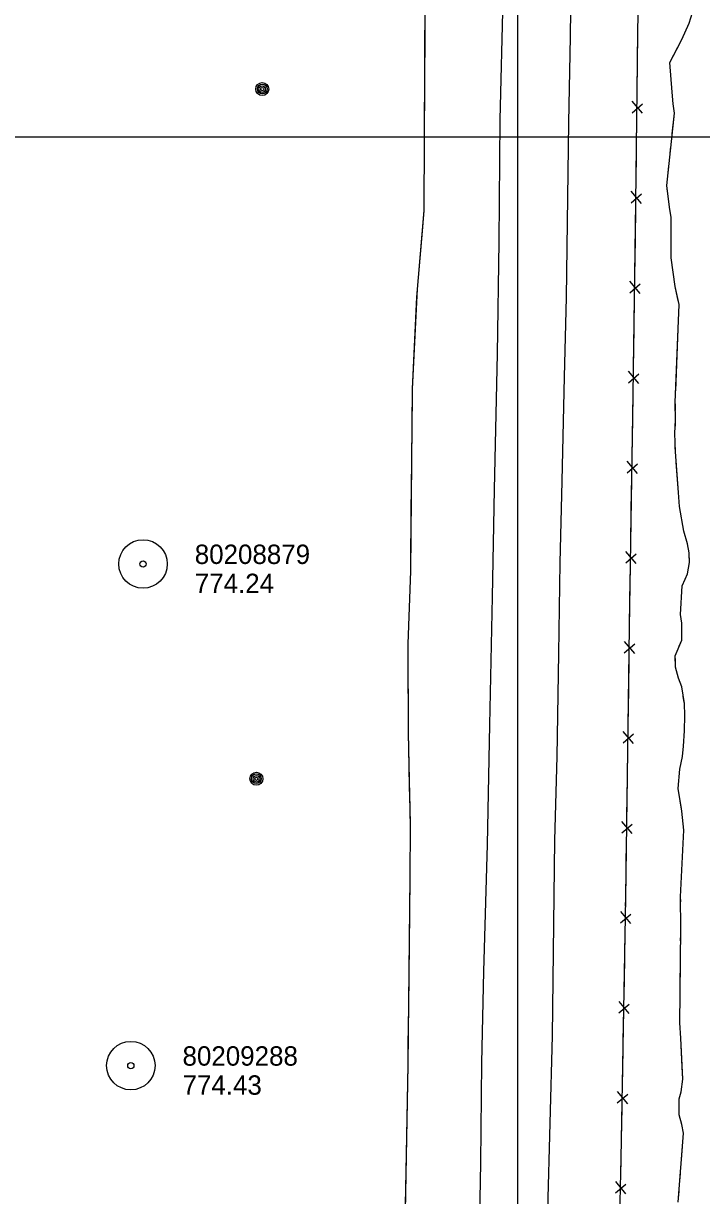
# Model space of a CAD drawing. Extents: x 591954 to 597000, y 198576 to 213500.
# Drawn here: x 593847 to 594056.8, y 208672.4 to 209035.1 of the extents above; entities that cross this region are included whole.
import ezdxf

# ---------------------------------------------------------------- set-up
doc = ezdxf.new("R2010")
doc.units = 0
for name, color, linetype in [('Level 10', 7, 'Continuous'), ('Level 11', 7, 'Continuous'), ('Level 14', 7, 'Continuous'), ('Level 15', 7, 'Continuous'), ('Level 19', 7, 'Continuous'), ('Level 6', 7, 'Continuous')]:
    doc.layers.add(name, color=color, linetype=linetype)

msp = doc.modelspace()

# ---------------------------------------------------------------- linework, layer by layer
at = {"layer": 'Level 10'}
for p, q in [((594000, 208500), (594000, 210000)), ((593000, 209000), (595000, 209000)), ((593000, 209000), (595000, 209000)), ((594000, 207500), (594000, 209000))]:
    msp.add_line(p, q, dxfattribs=at)
at = {"layer": 'Level 11'}
for points in [[(594009.01, 208631.52), (594009.27, 208667.78), (594010.66, 208721.83), (594011.4, 208782.36), (594012.13, 208808.26), (594012.62, 208840.15), (594013.04, 208868.19), (594013.68, 208893.39), (594014.42, 208925.71), (594015, 208950.25), (594015.72, 209004.45), (594016.24, 209030.86), (594016.62, 209056.33), (594017.53, 209087.3), (594018.52, 209145.92), (594019.42, 209185.52), (594019.83, 209212.01), (594020.29, 209245.3), (594020.92, 209277.11)], [(593998.85, 209230.64), (593998.3, 209195.94), (593997.61, 209162.68), (593996.73, 209120.37), (593996.08, 209080.6), (593995.31, 209042.89), (593994.35, 209005.26), (593994.1, 208967.53), (593993.55, 208932.78), (593992.64, 208890.84), (593992, 208857.63), (593991.15, 208818.04), (593990.48, 208781.03), (593989.3, 208741.66), (593988.74, 208713.42), (593988.39, 208682.48), (593987.81, 208648.94), (593987.57, 208630.06)]]:
    msp.add_lwpolyline(points, dxfattribs=at)
at = {"layer": 'Level 14'}
for centre, radius in [((593920.87, 209014.76), 2.02), ((593920.87, 209014.77), 1.52), ((593920.87, 209014.74), 1.01), ((593920.88, 209014.74), 0.502), ((593919.05, 208801.34), 2.02), ((593919.05, 208801.35), 1.52), ((593919.06, 208801.31), 1.01), ((593919.06, 208801.32), 0.502)]:
    msp.add_circle(centre, radius, dxfattribs=at)
at = {"layer": 'Level 15'}
for p, q in [((594035.32, 209007.44), (594038.52, 209010.2)), ((594038.56, 209007.24), (594035.36, 209010.99)), ((594035, 208979.59), (594038.2, 208982.35)), ((594038.24, 208979.38), (594035.04, 208983.13)), ((594034.59, 208951.73), (594037.81, 208954.48)), ((594037.83, 208951.52), (594034.65, 208955.28)), ((594034.19, 208923.88), (594037.4, 208926.63)), ((594037.42, 208923.66), (594034.24, 208927.42)), ((594033.76, 208896.02), (594036.98, 208898.77)), ((594037, 208895.8), (594033.82, 208899.57)), ((594033.34, 208868.17), (594036.55, 208870.91)), ((594036.57, 208867.95), (594033.39, 208871.71)), ((594036.16, 208840.09), (594032.97, 208843.85)), ((594032.92, 208840.31), (594036.13, 208843.06)), ((594032.54, 208812.45), (594035.75, 208815.2)), ((594035.77, 208812.23), (594032.59, 208816)), ((594032.15, 208784.59), (594035.36, 208787.34)), ((594035.39, 208784.38), (594032.2, 208788.14)), ((594034.97, 208756.51), (594031.8, 208760.29)), ((594031.74, 208756.74), (594034.95, 208759.48)), ((594031.24, 208728.88), (594034.46, 208731.62)), ((594034.47, 208728.66), (594031.3, 208732.43)), ((594030.74, 208701.03), (594033.96, 208703.77)), ((594033.97, 208700.8), (594030.8, 208704.58)), ((594033.42, 208672.94), (594030.27, 208676.73)), ((594030.19, 208673.18), (594033.42, 208675.9))]:
    msp.add_line(p, q, dxfattribs=at)
for points in [[(594030.79, 208634.01), (594031.94, 208683.98), (594033.37, 208764.41), (594034.53, 208848.11), (594035.64, 208920.32), (594036.5, 208979.5), (594037.1, 209031.73), (594037.78, 209078.39), (594038.97, 209145.83), (594039.39, 209201.19), (594040, 209259.04), (594040.17, 209306.37), (594041.42, 209344.67), (594041.5, 209389.61), (594042.2, 209438.38), (594043.44, 209486.71), (594045.27, 209558.54)], [(594037.01, 209024), (594037.1, 209031.73), (594037.13, 209033.96)], [(594036.88, 209012.68), (594037.01, 209024)], [(594036.69, 208996.14), (594036.8, 209006.1)], [(594036.56, 208984.82), (594036.69, 208996.14)], [(594036.33, 208968.28), (594036.48, 208978.24)], [(594036.17, 208956.96), (594036.33, 208968.28)], [(594035.93, 208940.43), (594036.07, 208950.38)], [(594035.76, 208929.11), (594035.93, 208940.43)], [(594035.52, 208912.57), (594035.64, 208920.32), (594035.67, 208922.52)], [(594035.34, 208901.25), (594035.52, 208912.57)], [(594035.09, 208884.71), (594035.24, 208894.67)], [(594034.92, 208873.39), (594035.09, 208884.71)], [(594034.66, 208856.86), (594034.82, 208866.81)], [(594034.49, 208845.54), (594034.53, 208848.11), (594034.66, 208856.86)], [(594034.27, 208829), (594034.4, 208838.96)], [(594034.11, 208817.68), (594034.27, 208829)], [(594033.88, 208801.14), (594034.02, 208811.1)], [(594033.72, 208789.82), (594033.88, 208801.14)], [(594033.5, 208773.28), (594033.63, 208783.24)], [(594033.33, 208761.96), (594033.37, 208764.41), (594033.5, 208773.28)], [(594033.03, 208745.43), (594033.21, 208755.38)], [(594032.83, 208734.11), (594033.03, 208745.43)], [(594032.54, 208717.57), (594032.71, 208727.53)], [(594032.33, 208706.25), (594032.54, 208717.57)], [(594032.04, 208689.72), (594032.22, 208699.67)], [(594031.81, 208678.4), (594031.94, 208683.98), (594032.04, 208689.72)]]:
    msp.add_lwpolyline(points, dxfattribs=at)
at = {"layer": 'Level 19'}
for p, q in [((593971.17, 209038.7), (593971.14, 209032.7)), ((593971.14, 209032.7), (593970.98, 208999.7)), ((593970.32, 208970.73), (593969.81, 208964.75)), ((593969.81, 208964.75), (593969.3, 208958.77)), ((593969.3, 208958.77), (593968.79, 208952.79)), ((593967.22, 208919.83), (593966.94, 208890.83)), ((593966.94, 208890.83), (593966.88, 208884.83)), ((593966.88, 208884.83), (593966.83, 208878.83)), ((593966.83, 208878.83), (593966.77, 208872.83)), ((593966.09, 208810.85), (593966.23, 208804.85)), ((593966.23, 208804.85), (593966.38, 208798.85)), ((593966.38, 208798.85), (593966.53, 208792.85)), ((593966.41, 208759.86), (593966.09, 208730.86)), ((593966.09, 208730.86), (593966.02, 208724.86)), ((593966.02, 208724.86), (593965.96, 208718.86)), ((593965.96, 208718.86), (593965.89, 208712.86)), ((593965.89, 208712.86), (593965.29, 208679.86)), ((593965.29, 208679.86), (593964.75, 208650.87))]:
    msp.add_line(p, q, dxfattribs=at)
for points in [[(593975.8, 209239.61), (593975.31, 209230.02), (593975.08, 209223.36), (593974.82, 209218.94), (593974.39, 209199.99), (593974.65, 209179.67), (593974.54, 209161.11), (593974.09, 209136.67), (593973.75, 209125.41), (593972.98, 209109.24), (593971.31, 209066.7), (593970.86, 208977.14), (593968.59, 208950.35), (593967.24, 208921.98), (593966.7, 208865.53), (593965.91, 208843.14), (593965.98, 208815.45), (593966.68, 208786.54), (593966.53, 208770.93), (593965.89, 208712.84), (593964.64, 208644.79), (593963.27, 208633.42), (593963.54, 208628.1)], [(594050.16, 209029.01), (594050.72, 209030.09), (594053.02, 209035.09), (594054.05, 209038.48), (594054.16, 209042.33), (594053.75, 209044.46), (594051.26, 209046.33)], [(594049.62, 208670.34), (594051.22, 208691.65), (594050.74, 208694.34), (594049.92, 208697.34), (594049.86, 208702.35), (594050.5, 208704.45), (594051.02, 208708.41), (594050.45, 208721.03), (594050.13, 208725.79), (594050.18, 208734.84), (594050.39, 208755.09), (594050.35, 208764.79), (594051.34, 208785.46), (594050.77, 208791.33), (594049.58, 208798.29), (594050.12, 208804.36), (594050.94, 208808.25), (594051.27, 208811.41), (594051.56, 208816.21), (594051.62, 208820.94), (594051.51, 208824.64), (594050.74, 208829.79), (594049.7, 208832.45), (594048.8, 208835.92), (594048.7, 208839.42), (594050.72, 208844.18), (594050.7, 208849.52), (594050.28, 208852.12), (594050.85, 208861.05), (594051.76, 208863.07), (594052.51, 208864.71), (594053.06, 208868.25), (594052.99, 208871.2), (594052.45, 208874.03), (594051.39, 208877.95), (594050.02, 208885.6), (594049.73, 208889.9), (594048.73, 208902.54), (594048.55, 208908.24), (594048.78, 208912.33), (594048.7, 208917.81), (594049.62, 208940.58), (594049.85, 208948.1), (594048.69, 208953.61), (594047.44, 208962.53), (594047.46, 208971.24), (594047.38, 208974.99), (594046.92, 208978.2), (594046.03, 208984.89), (594048.46, 209007.24), (594048.06, 209010.21), (594047.76, 209013.8), (594046.96, 209022.94), (594050.72, 209030.09), (594053.02, 209035.09)], [(594047.77, 209000.91), (594048.46, 209007.24), (594048.06, 209010.21), (594047.76, 209013.8), (594046.96, 209022.94), (594050.16, 209029.01)], [(593970.98, 208999.7), (593970.86, 208977.14), (593970.32, 208970.73)], [(594047.12, 208994.95), (594047.34, 208996.93)], [(594046.47, 208988.98), (594046.69, 208990.97)], [(594046.28, 208983.02), (594046.03, 208984.89), (594046.04, 208985.01)], [(594049.39, 208950.26), (594048.69, 208953.61), (594047.44, 208962.53), (594047.46, 208971.24), (594047.38, 208974.99), (594046.92, 208978.2), (594046.81, 208979.06)], [(593968.79, 208952.79), (593967.24, 208921.98), (593967.22, 208919.83)], [(594048.85, 208921.33), (594049.62, 208940.58), (594049.85, 208948.1), (594049.39, 208950.26)], [(594048.74, 208915.33), (594048.71, 208917.33)], [(594048.61, 208909.33), (594048.72, 208911.33)], [(594048.7, 208903.34), (594048.64, 208905.34)], [(594053, 208870.7), (594052.99, 208871.2), (594052.45, 208874.03), (594051.39, 208877.95), (594050.02, 208885.6), (594049.73, 208889.9), (594048.98, 208899.35)], [(593966.77, 208872.83), (593966.7, 208865.53), (593965.91, 208843.14), (593965.91, 208839.85)], [(594049.94, 208842.32), (594050.72, 208844.18), (594050.7, 208849.52), (594050.28, 208852.12), (594050.85, 208861.05), (594051.76, 208863.07), (594052.51, 208864.71), (594053.06, 208868.25), (594053, 208870.7)], [(593965.91, 208839.85), (593965.98, 208815.45), (593966.09, 208810.85)], [(594048.78, 208836.58), (594048.72, 208838.58)], [(594050.34, 208830.81), (594049.7, 208832.45), (594049.64, 208832.68)], [(594051.46, 208824.94), (594051.17, 208826.92)], [(594050.63, 208792.17), (594049.58, 208798.29), (594050.12, 208804.36), (594050.94, 208808.25), (594051.27, 208811.41), (594051.56, 208816.21), (594051.62, 208820.94), (594051.62, 208820.95)], [(593966.53, 208792.85), (593966.68, 208786.54), (593966.53, 208770.93), (593966.41, 208759.86)], [(594050.36, 208763.23), (594050.35, 208764.79), (594051.34, 208785.46), (594050.77, 208791.33), (594050.63, 208792.17)], [(594050.38, 208757.23), (594050.37, 208759.23)], [(594050.35, 208751.23), (594050.37, 208753.23)], [(594050.29, 208745.23), (594050.31, 208747.23)], [(594050.85, 208712.25), (594050.45, 208721.03), (594050.13, 208725.79), (594050.18, 208734.84), (594050.24, 208741.23)], [(594050.61, 208683.56), (594051.22, 208691.65), (594050.74, 208694.34), (594049.92, 208697.34), (594049.86, 208702.35), (594050.5, 208704.45), (594051.02, 208708.41), (594050.85, 208712.25)], [(594050.16, 208677.58), (594050.31, 208679.57)], [(594049.71, 208671.6), (594049.86, 208673.59)]]:
    msp.add_lwpolyline(points, dxfattribs=at)
at = {"layer": 'Level 6'}
for centre, radius in [((593883.98, 208867.8), 7.5), ((593883.98, 208867.8), 7.5), ((593883.98, 208867.8), 0.96), ((593883.98, 208867.8), 0.96), ((593880.2, 208712.57), 7.5), ((593880.2, 208712.57), 7.5), ((593880.2, 208712.57), 0.96), ((593880.2, 208712.57), 0.96)]:
    msp.add_circle(centre, radius, dxfattribs=at)

# ---------------------------------------------------------------- texts
for s, p in [('80208879', (593899.98, 208867.8)), ('80208879', (593899.98, 208867.8)), ('774.24', (593899.98, 208858.8)), ('774.24', (593899.98, 208858.8)), ('80209288', (593896.2, 208712.57)), ('80209288', (593896.2, 208712.57)), ('774.43', (593896.2, 208703.57)), ('774.43', (593896.2, 208703.57))]:
    msp.add_text(s, height=6, dxfattribs=at).set_placement(p)

doc.saveas('drawing.dxf')
